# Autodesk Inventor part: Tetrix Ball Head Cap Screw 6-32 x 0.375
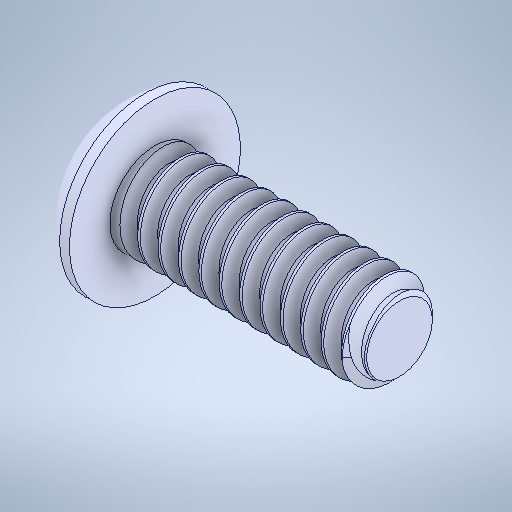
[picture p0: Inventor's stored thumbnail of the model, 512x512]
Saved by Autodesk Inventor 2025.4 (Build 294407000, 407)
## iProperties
Created: 2021-10
Part Number: Tetrix Ball Head Cap Screw 6-32 x 0.375
Material: Genérico
Document SubType Name: Modeling
Designer: usuario
Density: 1 g/cm^3
Appearance: Valor por defecto
Author: usuario
Sending System: SolidWorks 2016
Last Author: LENOVO
Last Saved: 2021-10-23
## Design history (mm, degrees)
feature "Cut-Revolve1"
node "Sólido1"
